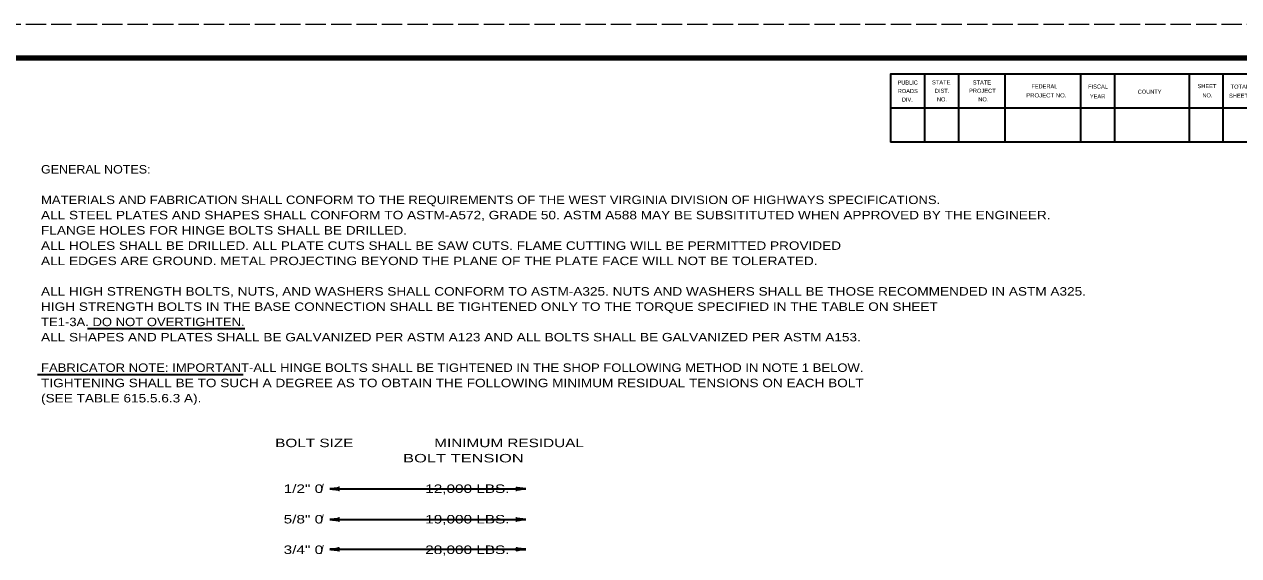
# Model space of a CAD drawing. Extents: x -2 to 835, y 0 to 440.
# Drawn here: x 298 to 656.1, y 282.9 to 439.6 of the extents above; entities that cross this region are included whole.
import ezdxf
from ezdxf.enums import TextEntityAlignment as Align

# ---------------------------------------------------------------- set-up
doc = ezdxf.new("R2010")
doc.units = 0
doc.linetypes.add('LONG_DASHED', pattern=[7.5, 6, -1.5])
doc.layers.add('1', color=7, linetype='Continuous', lineweight=53)
doc.layers.add('61', color=7, linetype='Continuous', lineweight=35)

msp = doc.modelspace()

# ---------------------------------------------------------------- linework, layer by layer
at = {"layer": '1', "lineweight": 35}
for p, q in [((316.635, 349.935), (363.063, 349.935)), ((301.921, 336.353), (362.565, 336.353)), ((388.09, 302.633), (445.846, 302.633)), ((388.09, 293.59), (445.846, 293.59)), ((388.09, 284.802), (445.846, 284.802))]:
    msp.add_line(p, q, dxfattribs=at)
at = {"layer": '1', "lineweight": 40}
for centre, major_axis, ratio, start_param, end_param in [((389.181, 302.909), (-1.786, -0.156), 0.122415, 0.8963533, 3.1415927), ((389.211, 302.421), (-1.756, 0.176), 0.07063, 3.1407148, 5.41811), ((444.755, 302.357), (1.786, 0.156), 0.122415, 0.8963533, 3.1415927), ((444.755, 302.357), (1.786, 0.156), 0.122415, 0.8963533, 3.1415927), ((444.725, 302.844), (1.756, -0.176), 0.07063, 3.1407148, 5.41811), ((444.725, 302.844), (1.756, -0.176), 0.07063, 3.1407148, 5.41811), ((389.181, 293.867), (-1.786, -0.156), 0.122415, 0.8963533, 3.1415927), ((389.211, 293.379), (-1.756, 0.176), 0.07063, 3.1407148, 5.41811), ((444.755, 293.314), (1.786, 0.156), 0.122415, 0.8963533, 3.1415927), ((444.755, 293.314), (1.786, 0.156), 0.122415, 0.8963533, 3.1415927), ((444.725, 293.802), (1.756, -0.176), 0.07063, 3.1407148, 5.41811), ((444.725, 293.802), (1.756, -0.176), 0.07063, 3.1407148, 5.41811), ((389.181, 285.078), (-1.786, -0.156), 0.122415, 0.8963533, 3.1415927), ((389.181, 285.078), (-1.786, -0.156), 0.122415, 0.8963533, 3.1415927), ((389.211, 284.59), (-1.756, 0.176), 0.07063, 3.1407148, 5.41811), ((389.211, 284.59), (-1.756, 0.176), 0.07063, 3.1407148, 5.41811), ((444.755, 284.525), (1.786, 0.156), 0.122415, 0.8963533, 3.1415927), ((444.755, 284.525), (1.786, 0.156), 0.122415, 0.8963533, 3.1415927), ((444.725, 285.013), (1.756, -0.176), 0.07063, 3.1407148, 5.41811), ((444.725, 285.013), (1.756, -0.176), 0.07063, 3.1407148, 5.41811)]:
    msp.add_ellipse(centre, major_axis=major_axis, ratio=ratio, start_param=start_param, end_param=end_param, dxfattribs=at)
at = {"layer": '61', "linetype": 'LONG_DASHED', "lineweight": 13}
msp.add_line((-1.527, 439.629), (678.493, 439.629), dxfattribs=at)
at = {"layer": '61'}
for p, q in [((563.433, 424.869), (563.433, 404.869)), ((573.433, 424.869), (573.433, 404.869)), ((587.113, 424.869), (587.113, 404.869)), ((609.433, 424.869), (609.433, 404.869)), ((619.433, 424.869), (619.433, 404.869)), ((641.413, 424.889), (641.413, 404.889)), ((651.413, 424.889), (651.413, 404.889)), ((661.433, 414.849), (553.413, 414.869))]:
    msp.add_line(p, q, dxfattribs=at)
at = {"layer": '61', "lineweight": 158}
msp.add_lwpolyline([(667.513, 429.629), (28.473, 429.629), (28.473, 9.609)], dxfattribs=at)
at = {"layer": '61'}
for points in [[(661.413, 424.889), (553.433, 424.869), (553.433, 404.869)], [(661.413, 424.889), (661.413, 404.889), (553.433, 404.869)]]:
    msp.add_lwpolyline(points, dxfattribs=at)

# ---------------------------------------------------------------- texts
at = {"layer": '1'}
for s, width, p in [('GENERAL NOTES:', 1.1, (302.967, 395.611)), ('MATERIALS AND FABRICATION SHALL CONFORM TO THE REQUIREMENTS OF THE WEST VIRGINIA DIVISION OF HIGHWAYS SPECIFICATIONS.', 1.15, (302.967, 386.611)), ('ALL STEEL PLATES AND SHAPES SHALL CONFORM TO ASTM-A572, GRADE 50. ASTM A588 MAY BE SUBSITITUTED WHEN APPROVED BY THE ENGINEER.', 1.2, (302.967, 382.111)), ('FLANGE HOLES FOR HINGE BOLTS SHALL BE DRILLED.', 1.2, (302.967, 377.611)), ('ALL HOLES SHALL BE DRILLED. ALL PLATE CUTS SHALL BE SAW CUTS. FLAME CUTTING WILL BE PERMITTED PROVIDED', 1.2, (302.967, 373.111)), ('ALL EDGES ARE GROUND. METAL PROJECTING BEYOND THE PLANE OF THE PLATE FACE WILL NOT BE TOLERATED.', 1.2, (302.967, 368.611)), ('ALL HIGH STRENGTH BOLTS, NUTS, AND WASHERS SHALL CONFORM TO ASTM-A325. NUTS AND WASHERS SHALL BE THOSE RECOMMENDED IN ASTM A325.', 1.2, (302.967, 359.611)), ('HIGH STRENGTH BOLTS IN THE BASE CONNECTION SHALL BE TIGHTENED ONLY TO THE TORQUE SPECIFIED IN THE TABLE ON SHEET', 1.2, (302.967, 355.111)), ('TE1-3A. DO NOT OVERTIGHTEN.', 1.15, (302.967, 350.611)), ('ALL SHAPES AND PLATES SHALL BE GALVANIZED PER ASTM A123 AND ALL BOLTS SHALL BE GALVANIZED PER ASTM A153.', 1.2, (302.967, 346.111)), ('FABRICATOR NOTE: IMPORTANT-ALL HINGE BOLTS SHALL BE TIGHTENED IN THE SHOP FOLLOWING METHOD IN NOTE 1 BELOW.', 1.15, (302.967, 337.111)), ('TIGHTENING SHALL BE TO SUCH A DEGREE AS TO OBTAIN THE FOLLOWING MINIMUM RESIDUAL TENSIONS ON EACH BOLT', 1.2, (302.967, 332.611)), ('(SEE TABLE 615.5.6.3 A).', 1.2, (302.967, 328.111)), ('BOLT SIZE                   MINIMUM RESIDUAL', 1.35, (371.994, 314.927)), ('                            BOLT TENSION', 1.45, (371.994, 310.427)), ('  1/2" 0                        12,000 LBS.', 1.35, (371.994, 301.427)), ('  5/8" 0                        19,000 LBS.', 1.35, (371.994, 292.427)), ('  3/4" 0                        28,000 LBS.', 1.35, (371.994, 283.427))]:
    msp.add_text(s, height=2.5, dxfattribs=dict(at, width=width)).set_placement(p)
for p in [(385.86, 301.513), (385.86, 292.508), (385.86, 283.459)]:
    msp.add_text('/', height=2.5, dxfattribs=at).set_placement(p, align=Align.CENTER)
at = {"layer": '61'}
for s, rotation, p in [('PUBLIC', 0.033, (555.473, 421.849)), ('ROADS', 0.124, (555.553, 419.329)), ('DIST.', 0.056, (566.513, 419.409)), ('FEDERAL', 0.007, (594.933, 420.729)), ('FISCAL', 359.942, (611.673, 420.669)), ('YEAR', 0.105, (612.193, 417.769)), ('COUNTY', 0.069, (626.293, 419.129)), ('SHEET', 0.059, (643.933, 420.789)), ('SHEETS', 359.959, (653.213, 417.949)), ('DIV.', 359.932, (556.753, 416.829))]:
    msp.add_text(s, height=1.201, rotation=rotation, dxfattribs=at).set_placement(p)
for s, rotation, width, p in [('STATE', 0.059, 1.05, (565.633, 421.909)), ('STATE', 0.059, 1.05, (577.633, 421.849)), ('PROJECT', 359.908, 1.05, (576.553, 419.429)), ('PROJECT NO.', 359.922, 1.1, (593.393, 418.069)), ('NO.', 359.852, 0.95, (645.353, 418.069)), ('TOTAL', 359.926, 1.05, (653.673, 420.649)), ('NO.', 359.852, 0.95, (567.093, 416.889)), ('NO.', 0.225, 0.95, (579.293, 416.889))]:
    msp.add_text(s, height=1.201, rotation=rotation, dxfattribs=dict(at, width=width)).set_placement(p)

doc.saveas('drawing.dxf')
